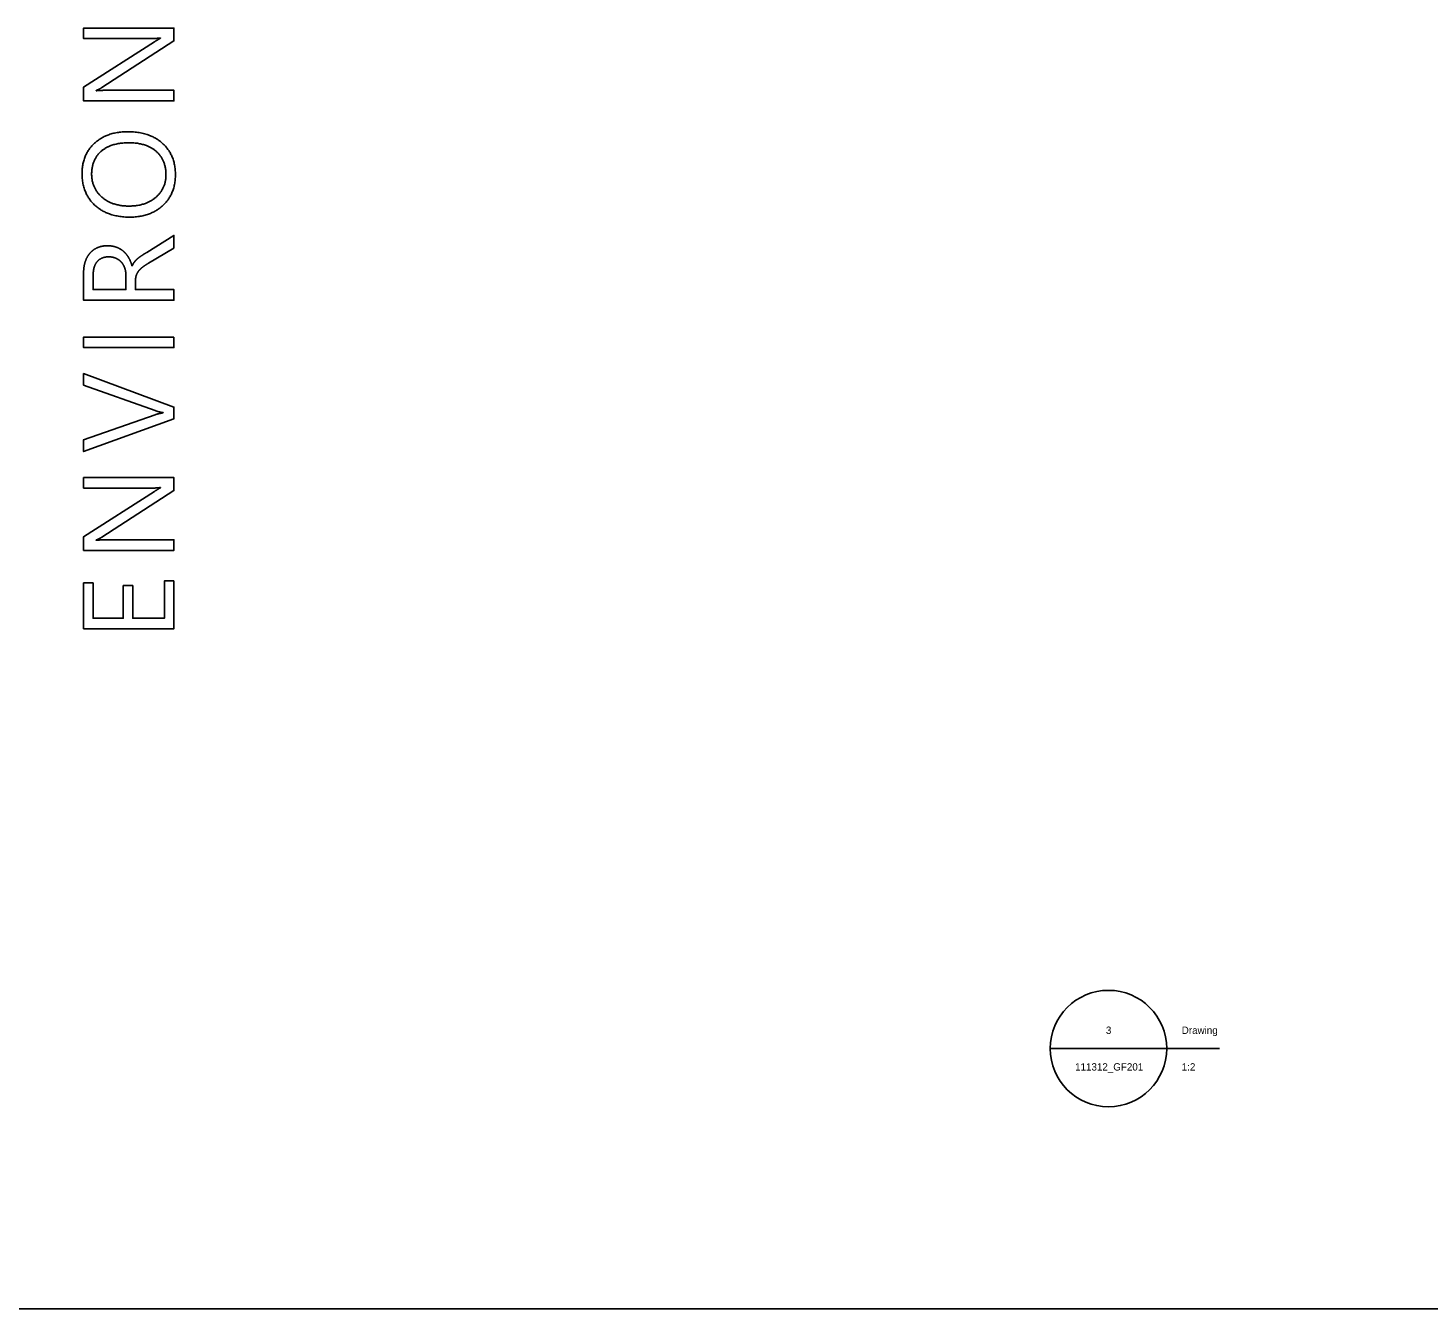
# Model space of a CAD drawing. Extents: x -5.2 to 34, y 0 to 22.
# Drawn here: x 32.546 to 33.173, y 2.5 to 3.073 of the extents above; entities that cross this region are included whole.
import ezdxf

# ---------------------------------------------------------------- set-up
doc = ezdxf.new("R2010")
doc.units = 0
for name, color, linetype in [('CS-ANNO', 7, 'Continuous'), ('CS-ANNO-MATC', 7, 'Continuous'), ('CS-ANNO-VFRM', 7, 'Continuous')]:
    doc.layers.add(name, color=color, linetype=linetype)

msp = doc.modelspace()

# ---------------------------------------------------------------- linework, layer by layer
at = {"layer": 'CS-ANNO'}
msp.add_line((32, 2.5), (33.5, 2.5), dxfattribs=at)
at = {"layer": 'CS-ANNO-MATC'}
for p, q in [((32.60573, 3.06851), (32.60573, 3.06862)), ((32.57697, 3.04516), (32.57697, 3.04499)), ((32.57492, 3.00774), (32.57492, 3.00774)), ((32.61241, 3.00741), (32.61241, 3.00741)), ((32.59307, 2.96669), (32.59296, 2.96669)), ((32.60694, 2.90089), (32.60694, 2.901)), ((32.60573, 2.86739), (32.60573, 2.8675)), ((32.57697, 2.84404), (32.57697, 2.84387))]:
    msp.add_line(p, q, dxfattribs=at)
for points in [[(32.59978, 3.06834), (32.57131, 3.06834), (32.57131, 3.07307), (32.61174, 3.07307), (32.61174, 3.06727), (32.57951, 3.04646)], [(32.58253, 3.04522), (32.61174, 3.04522), (32.61174, 3.04048), (32.57131, 3.04048), (32.57131, 3.04663), (32.60302, 3.06687)], [(32.6004, 2.96788), (32.61174, 2.97464), (32.61174, 2.98028), (32.59959, 2.9727)], [(32.57131, 2.96337), (32.57131, 2.9513), (32.61174, 2.9513), (32.61174, 2.95604), (32.59454, 2.95604), (32.59454, 2.95993)], [(32.59025, 2.96246), (32.59025, 2.95604), (32.57559, 2.95604), (32.57559, 2.96252)], [(32.60331, 2.90193), (32.57131, 2.91335), (32.57131, 2.91845), (32.61174, 2.90348), (32.61174, 2.89827), (32.57131, 2.88361), (32.57131, 2.88888), (32.60336, 2.90007)], [(32.59978, 2.86722), (32.57131, 2.86722), (32.57131, 2.87196), (32.61174, 2.87196), (32.61174, 2.86615), (32.57951, 2.84534)], [(32.58253, 2.8441), (32.61174, 2.8441), (32.61174, 2.83936), (32.57131, 2.83936), (32.57131, 2.84551), (32.60302, 2.86575)]]:
    msp.add_lwpolyline(points, dxfattribs=at)
for points in [[(32.61174, 2.93482), (32.61174, 2.93008), (32.57131, 2.93008), (32.57131, 2.93482)], [(32.61174, 2.82574), (32.61174, 2.80431), (32.57131, 2.80431), (32.57131, 2.82484), (32.57559, 2.82484), (32.57559, 2.80905), (32.58904, 2.80905), (32.58904, 2.82365), (32.5933, 2.82365), (32.5933, 2.80905), (32.60745, 2.80905), (32.60745, 2.82574)]]:
    msp.add_lwpolyline(points, close=True, dxfattribs=at)
for points in [[(32.60573, 3.06862), (32.60398, 3.06834), (32.59978, 3.06834)], [(32.60302, 3.06687), (32.605, 3.06814), (32.60573, 3.06851)], [(32.57951, 3.04646), (32.5783, 3.04567), (32.57697, 3.04516)], [(32.57697, 3.04499), (32.57827, 3.04522), (32.58253, 3.04522)], [(32.59101, 3.02669), (32.58191, 3.02669), (32.57627, 3.02157)], [(32.60666, 3.02145), (32.60091, 3.02669), (32.59101, 3.02669)], [(32.57627, 3.02157), (32.57063, 3.01646), (32.57063, 3.00808)], [(32.57929, 3.01801), (32.58366, 3.02173), (32.59166, 3.02173)], [(32.59166, 3.02173), (32.59947, 3.02173), (32.60381, 3.01789)], [(32.61241, 3.00741), (32.61241, 3.0162), (32.60666, 3.02145)], [(32.57492, 3.00774), (32.57492, 3.01428), (32.57929, 3.01801)], [(32.60381, 3.01789), (32.60816, 3.01406), (32.60816, 3.00741)], [(32.57063, 3.00808), (32.57063, 2.999), (32.57644, 2.99373)], [(32.57951, 2.9974), (32.57492, 3.00137), (32.57492, 3.00774)], [(32.60816, 3.00741), (32.60816, 3.00117), (32.6036, 2.9973)], [(32.60675, 2.99363), (32.61241, 2.99881), (32.61241, 3.00741)], [(32.59158, 2.99342), (32.58411, 2.99342), (32.57951, 2.9974)], [(32.6036, 2.9973), (32.59905, 2.99342), (32.59158, 2.99342)], [(32.57644, 2.99373), (32.58225, 2.98846), (32.592, 2.98846)], [(32.592, 2.98846), (32.60108, 2.98846), (32.60675, 2.99363)], [(32.58208, 2.97566), (32.57937, 2.97566), (32.57735, 2.97473)], [(32.58595, 2.97502), (32.58419, 2.97566), (32.58208, 2.97566)], [(32.57399, 2.97215), (32.57263, 2.9705), (32.57197, 2.96826)], [(32.57735, 2.97473), (32.57534, 2.9738), (32.57399, 2.97215)], [(32.57741, 2.9686), (32.57923, 2.9707), (32.58247, 2.9707)], [(32.58247, 2.9707), (32.58428, 2.9707), (32.58573, 2.97008)], [(32.58573, 2.97008), (32.58718, 2.96945), (32.58818, 2.96836)], [(32.5891, 2.97322), (32.58772, 2.97439), (32.58595, 2.97502)], [(32.59145, 2.9704), (32.59048, 2.97205), (32.5891, 2.97322)], [(32.59296, 2.96669), (32.59242, 2.96875), (32.59145, 2.9704)], [(32.59547, 2.96988), (32.59468, 2.9692), (32.5941, 2.96845)], [(32.59726, 2.97122), (32.59626, 2.97055), (32.59547, 2.96988)], [(32.59959, 2.9727), (32.59826, 2.97188), (32.59726, 2.97122)], [(32.57197, 2.96826), (32.57131, 2.96602), (32.57131, 2.96337)], [(32.57559, 2.96252), (32.57559, 2.96649), (32.57741, 2.9686)], [(32.58818, 2.96836), (32.58918, 2.96726), (32.58972, 2.96575)], [(32.58972, 2.96575), (32.59025, 2.96424), (32.59025, 2.96246)], [(32.5941, 2.96845), (32.59352, 2.96771), (32.59307, 2.96669)], [(32.59486, 2.96231), (32.59519, 2.96337), (32.59589, 2.96428)], [(32.59589, 2.96428), (32.5966, 2.9652), (32.59771, 2.96607)], [(32.59771, 2.96607), (32.59882, 2.96695), (32.6004, 2.96788)], [(32.59454, 2.95993), (32.59454, 2.96125), (32.59486, 2.96231)], [(32.60694, 2.901), (32.60525, 2.90123), (32.60331, 2.90193)], [(32.60336, 2.90007), (32.60491, 2.90061), (32.60694, 2.90089)], [(32.60573, 2.8675), (32.60398, 2.86722), (32.59978, 2.86722)], [(32.60302, 2.86575), (32.605, 2.86702), (32.60573, 2.86739)], [(32.57951, 2.84534), (32.5783, 2.84455), (32.57697, 2.84404)], [(32.57697, 2.84387), (32.57827, 2.8441), (32.58253, 2.8441)]]:
    msp.add_open_spline(points, degree=2, dxfattribs=at)
at = {"layer": 'CS-ANNO-VFRM'}
for p, q in [((33.00385, 2.61651), (33.05593, 2.61651)), ((33.03012, 2.61651), (33.07959, 2.61651))]:
    msp.add_line(p, q, dxfattribs=at)
msp.add_circle((33.02989, 2.61651), 0.02604, dxfattribs=at)

# ---------------------------------------------------------------- texts
for s, height, p in [('3', 0.00328, (33.02872, 2.62307)), ('Drawing', 0.003281, (33.06267, 2.62307)), ('111312_GF201', 0.0032808, (33.01495, 2.60667)), ('1:2', 0.003281, (33.06267, 2.60667))]:
    msp.add_text(s, height=height, dxfattribs=at).set_placement(p)

doc.saveas('drawing.dxf')
